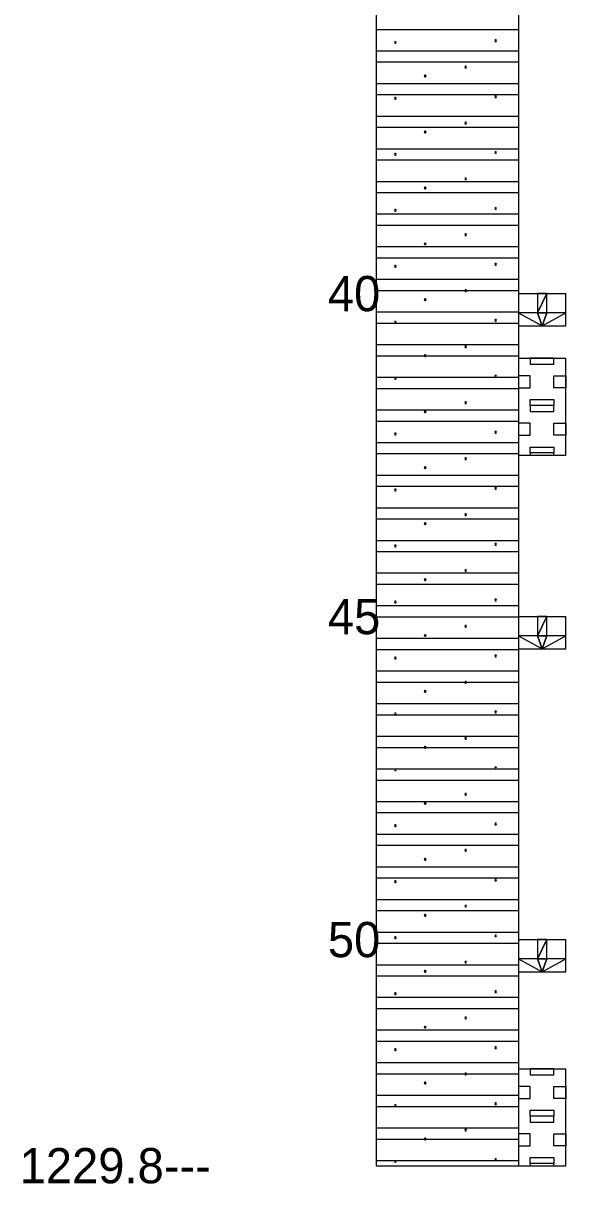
# Model space of a CAD drawing. Extents: x 2150161.5 to 2150203.1, y 143779.5 to 143868.5.
# Drawn here: x 2150190.718 to 2150192.627, y 143817.137 to 143821.22 of the extents above; entities that cross this region are included whole.
import ezdxf

# ---------------------------------------------------------------- set-up
doc = ezdxf.new("R2010")
doc.units = 0
doc.layers.add('Default', color=7, linetype='Continuous')

msp = doc.modelspace()

# ---------------------------------------------------------------- linework, layer by layer
at = {"layer": 'Default'}
for points in [[(2150191.9604, 143829.3595), (2150191.9604, 143817.2004)], [(2150192.4604, 143829.3595), (2150192.4604, 143817.2004)], [(2150191.9604, 143821.1983), (2150192.4604, 143821.1983)], [(2150192.0308, 143821.1521), (2150192.0292, 143821.1549), (2150192.0259, 143821.1549), (2150192.0243, 143821.1521), (2150192.0259, 143821.1492), (2150192.0292, 143821.1492), (2150192.0308, 143821.1521)], [(2150192.3836, 143821.1586), (2150192.3819, 143821.1615), (2150192.3787, 143821.1615), (2150192.377, 143821.1586), (2150192.3787, 143821.1558), (2150192.3819, 143821.1558), (2150192.3836, 143821.1586)], [(2150191.9604, 143821.1228), (2150192.4604, 143821.1228)], [(2150191.9604, 143821.0835), (2150192.4604, 143821.0835)], [(2150192.2781, 143821.0661), (2150192.2764, 143821.0689), (2150192.2731, 143821.0689), (2150192.2715, 143821.0661), (2150192.2731, 143821.0632), (2150192.2764, 143821.0632), (2150192.2781, 143821.0661)], [(2150192.1355, 143821.0342), (2150192.1338, 143821.0371), (2150192.1306, 143821.0371), (2150192.1289, 143821.0342), (2150192.1306, 143821.0314), (2150192.1338, 143821.0314), (2150192.1355, 143821.0342)], [(2150191.9604, 143821.008), (2150192.4604, 143821.008)], [(2150191.9604, 143820.9686), (2150192.4604, 143820.9686)], [(2150192.0308, 143820.9552), (2150192.0292, 143820.9581), (2150192.0259, 143820.9581), (2150192.0243, 143820.9552), (2150192.0259, 143820.9524), (2150192.0292, 143820.9524), (2150192.0308, 143820.9552)], [(2150192.3836, 143820.9617), (2150192.3819, 143820.9646), (2150192.3787, 143820.9646), (2150192.377, 143820.9617), (2150192.3787, 143820.9589), (2150192.3819, 143820.9589), (2150192.3836, 143820.9617)], [(2150191.9604, 143820.8932), (2150192.4604, 143820.8932)], [(2150191.9604, 143820.8538), (2150192.4604, 143820.8538)], [(2150192.2781, 143820.8692), (2150192.2764, 143820.872), (2150192.2731, 143820.872), (2150192.2715, 143820.8692), (2150192.2731, 143820.8664), (2150192.2764, 143820.8664), (2150192.2781, 143820.8692)], [(2150192.1355, 143820.8373), (2150192.1338, 143820.8402), (2150192.1306, 143820.8402), (2150192.1289, 143820.8374), (2150192.1306, 143820.8345), (2150192.1338, 143820.8345), (2150192.1355, 143820.8373)], [(2150191.9604, 143820.7783), (2150192.4604, 143820.7783)], [(2150192.3836, 143820.7649), (2150192.3819, 143820.7678), (2150192.3787, 143820.7678), (2150192.377, 143820.7649), (2150192.3787, 143820.7621), (2150192.3819, 143820.7621), (2150192.3836, 143820.7649)], [(2150191.9604, 143820.739), (2150192.4604, 143820.739)], [(2150192.0308, 143820.7584), (2150192.0292, 143820.7612), (2150192.0259, 143820.7612), (2150192.0243, 143820.7584), (2150192.0259, 143820.7555), (2150192.0292, 143820.7555), (2150192.0308, 143820.7584)], [(2150191.9604, 143820.6635), (2150192.4604, 143820.6635)], [(2150192.1355, 143820.6405), (2150192.1338, 143820.6434), (2150192.1306, 143820.6434), (2150192.1289, 143820.6405), (2150192.1306, 143820.6377), (2150192.1338, 143820.6377), (2150192.1355, 143820.6405)], [(2150192.2781, 143820.6724), (2150192.2764, 143820.6752), (2150192.2731, 143820.6752), (2150192.2715, 143820.6724), (2150192.2731, 143820.6695), (2150192.2764, 143820.6695), (2150192.2781, 143820.6724)], [(2150191.9604, 143820.6241), (2150192.4604, 143820.6241)], [(2150192.0308, 143820.5615), (2150192.0292, 143820.5644), (2150192.0259, 143820.5644), (2150192.0243, 143820.5615), (2150192.0259, 143820.5587), (2150192.0292, 143820.5587), (2150192.0308, 143820.5615)], [(2150192.3836, 143820.568), (2150192.3819, 143820.5709), (2150192.3787, 143820.5709), (2150192.377, 143820.568), (2150192.3787, 143820.5652), (2150192.3819, 143820.5652), (2150192.3836, 143820.568)], [(2150191.9604, 143820.5487), (2150192.4604, 143820.5487)], [(2150191.9604, 143820.5093), (2150192.4604, 143820.5093)], [(2150192.2781, 143820.4755), (2150192.2764, 143820.4783), (2150192.2731, 143820.4783), (2150192.2715, 143820.4755), (2150192.2731, 143820.4727), (2150192.2764, 143820.4727), (2150192.2781, 143820.4755)], [(2150192.1355, 143820.4436), (2150192.1338, 143820.4465), (2150192.1306, 143820.4465), (2150192.1289, 143820.4437), (2150192.1306, 143820.4408), (2150192.1338, 143820.4408), (2150192.1355, 143820.4436)], [(2150191.9604, 143820.4339), (2150192.4604, 143820.4339)], [(2150191.9604, 143820.3945), (2150192.4604, 143820.3945)], [(2150192.0308, 143820.3647), (2150192.0292, 143820.3675), (2150192.0259, 143820.3675), (2150192.0243, 143820.3647), (2150192.0259, 143820.3618), (2150192.0292, 143820.3618), (2150192.0308, 143820.3647)], [(2150192.3836, 143820.3712), (2150192.3819, 143820.3741), (2150192.3787, 143820.3741), (2150192.377, 143820.3712), (2150192.3787, 143820.3684), (2150192.3819, 143820.3684), (2150192.3836, 143820.3712)], [(2150191.9604, 143820.319), (2150192.4604, 143820.319)], [(2150191.9604, 143820.2797), (2150192.4604, 143820.2797)], [(2150192.2781, 143820.2787), (2150192.2764, 143820.2815), (2150192.2731, 143820.2815), (2150192.2715, 143820.2787), (2150192.2731, 143820.2758), (2150192.2764, 143820.2758), (2150192.2781, 143820.2787)], [(2150192.1355, 143820.2468), (2150192.1338, 143820.2497), (2150192.1306, 143820.2497), (2150192.1289, 143820.2468), (2150192.1306, 143820.244), (2150192.1338, 143820.244), (2150192.1355, 143820.2468)], [(2150192.4604, 143820.2686), (2150192.6271, 143820.2686)], [(2150192.6271, 143820.155), (2150192.6271, 143820.2686)], [(2150191.9604, 143820.2042), (2150192.4604, 143820.2042)], [(2150191.9604, 143820.1648), (2150192.4604, 143820.1648)], [(2150192.0308, 143820.1678), (2150192.0292, 143820.1707), (2150192.0259, 143820.1707), (2150192.0243, 143820.1678), (2150192.0259, 143820.165), (2150192.0292, 143820.165), (2150192.0308, 143820.1678)], [(2150192.3836, 143820.1743), (2150192.3819, 143820.1772), (2150192.3787, 143820.1772), (2150192.377, 143820.1743), (2150192.3787, 143820.1715), (2150192.3819, 143820.1715), (2150192.3836, 143820.1743)], [(2150192.4604, 143820.155), (2150192.6271, 143820.155)], [(2150191.9604, 143820.0894), (2150192.4604, 143820.0894)], [(2150192.2781, 143820.0818), (2150192.2764, 143820.0846), (2150192.2731, 143820.0846), (2150192.2715, 143820.0818), (2150192.2731, 143820.079), (2150192.2764, 143820.079), (2150192.2781, 143820.0818)], [(2150191.9604, 143820.05), (2150192.4604, 143820.05)], [(2150192.1355, 143820.0499), (2150192.1338, 143820.0528), (2150192.1306, 143820.0528), (2150192.1289, 143820.05), (2150192.1306, 143820.0471), (2150192.1338, 143820.0471), (2150192.1355, 143820.0499)], [(2150192.4604, 143820.0413), (2150192.6271, 143820.0413)], [(2150192.6271, 143819.7004), (2150192.6271, 143820.0413)], [(2150191.9604, 143819.9745), (2150192.4604, 143819.9745)], [(2150192.0308, 143819.971), (2150192.0292, 143819.9738), (2150192.0259, 143819.9738), (2150192.0243, 143819.971), (2150192.0259, 143819.9681), (2150192.0292, 143819.9681), (2150192.0308, 143819.971)], [(2150192.3836, 143819.9775), (2150192.3819, 143819.9804), (2150192.3787, 143819.9804), (2150192.377, 143819.9775), (2150192.3787, 143819.9747), (2150192.3819, 143819.9747), (2150192.3836, 143819.9775)], [(2150191.9604, 143819.9352), (2150192.4604, 143819.9352)], [(2150192.2781, 143819.885), (2150192.2764, 143819.8878), (2150192.2731, 143819.8878), (2150192.2715, 143819.885), (2150192.2731, 143819.8821), (2150192.2764, 143819.8821), (2150192.2781, 143819.885)], [(2150191.9604, 143819.8597), (2150192.4604, 143819.8597)], [(2150192.1355, 143819.8531), (2150192.1338, 143819.856), (2150192.1306, 143819.856), (2150192.1289, 143819.8531), (2150192.1306, 143819.8503), (2150192.1338, 143819.8503), (2150192.1355, 143819.8531)], [(2150191.9604, 143819.8203), (2150192.4604, 143819.8203)], [(2150191.9604, 143819.7449), (2150192.4604, 143819.7449)], [(2150192.0308, 143819.7741), (2150192.0292, 143819.777), (2150192.0259, 143819.777), (2150192.0243, 143819.7741), (2150192.0259, 143819.7713), (2150192.0292, 143819.7713), (2150192.0308, 143819.7741)], [(2150192.3836, 143819.7806), (2150192.3819, 143819.7835), (2150192.3787, 143819.7835), (2150192.377, 143819.7806), (2150192.3787, 143819.7778), (2150192.3819, 143819.7778), (2150192.3836, 143819.7806)], [(2150191.9604, 143819.7055), (2150192.4604, 143819.7055)], [(2150192.2781, 143819.6881), (2150192.2764, 143819.6909), (2150192.2731, 143819.6909), (2150192.2715, 143819.6881), (2150192.2731, 143819.6853), (2150192.2764, 143819.6853), (2150192.2781, 143819.6881)], [(2150192.4604, 143819.7004), (2150192.6271, 143819.7004)], [(2150191.9604, 143819.63), (2150192.4604, 143819.63)], [(2150192.1355, 143819.6562), (2150192.1338, 143819.6591), (2150192.1306, 143819.6591), (2150192.1289, 143819.6563), (2150192.1306, 143819.6534), (2150192.1338, 143819.6534), (2150192.1355, 143819.6562)], [(2150191.9604, 143819.5907), (2150192.4604, 143819.5907)], [(2150192.0308, 143819.5773), (2150192.0292, 143819.5801), (2150192.0259, 143819.5801), (2150192.0243, 143819.5773), (2150192.0259, 143819.5744), (2150192.0292, 143819.5744), (2150192.0308, 143819.5773)], [(2150192.3836, 143819.5838), (2150192.3819, 143819.5867), (2150192.3787, 143819.5867), (2150192.377, 143819.5838), (2150192.3787, 143819.581), (2150192.3819, 143819.581), (2150192.3836, 143819.5838)], [(2150191.9604, 143819.5152), (2150192.4604, 143819.5152)], [(2150191.9604, 143819.4758), (2150192.4604, 143819.4758)], [(2150192.1355, 143819.4594), (2150192.1338, 143819.4623), (2150192.1306, 143819.4623), (2150192.1289, 143819.4594), (2150192.1306, 143819.4566), (2150192.1338, 143819.4566), (2150192.1355, 143819.4594)], [(2150192.2781, 143819.4913), (2150192.2764, 143819.4941), (2150192.2731, 143819.4941), (2150192.2715, 143819.4913), (2150192.2731, 143819.4884), (2150192.2764, 143819.4884), (2150192.2781, 143819.4913)], [(2150191.9604, 143819.4004), (2150192.4604, 143819.4004)], [(2150192.0308, 143819.3804), (2150192.0292, 143819.3833), (2150192.0259, 143819.3833), (2150192.0243, 143819.3804), (2150192.0259, 143819.3776), (2150192.0292, 143819.3776), (2150192.0308, 143819.3804)], [(2150192.3836, 143819.3869), (2150192.3819, 143819.3898), (2150192.3787, 143819.3898), (2150192.377, 143819.3869), (2150192.3787, 143819.3841), (2150192.3819, 143819.3841), (2150192.3836, 143819.3869)], [(2150191.9604, 143819.361), (2150192.4604, 143819.361)], [(2150192.2781, 143819.2944), (2150192.2764, 143819.2972), (2150192.2731, 143819.2972), (2150192.2715, 143819.2944), (2150192.2731, 143819.2916), (2150192.2764, 143819.2916), (2150192.2781, 143819.2944)], [(2150191.9604, 143819.2856), (2150192.4604, 143819.2856)], [(2150192.1355, 143819.2625), (2150192.1338, 143819.2654), (2150192.1306, 143819.2654), (2150192.1289, 143819.2626), (2150192.1306, 143819.2597), (2150192.1338, 143819.2597), (2150192.1355, 143819.2625)], [(2150191.9604, 143819.2462), (2150192.4604, 143819.2462)], [(2150192.0308, 143819.1836), (2150192.0292, 143819.1864), (2150192.0259, 143819.1864), (2150192.0243, 143819.1836), (2150192.0259, 143819.1807), (2150192.0292, 143819.1807), (2150192.0308, 143819.1836)], [(2150192.3836, 143819.1901), (2150192.3819, 143819.193), (2150192.3787, 143819.193), (2150192.377, 143819.1901), (2150192.3787, 143819.1873), (2150192.3819, 143819.1873), (2150192.3836, 143819.1901)], [(2150191.9604, 143819.1707), (2150192.4604, 143819.1707)], [(2150191.9604, 143819.1314), (2150192.4604, 143819.1314)], [(2150192.4604, 143819.1323), (2150192.6271, 143819.1323)], [(2150192.6271, 143819.0186), (2150192.6271, 143819.1323)], [(2150192.2781, 143819.0976), (2150192.2764, 143819.1004), (2150192.2731, 143819.1004), (2150192.2715, 143819.0976), (2150192.2731, 143819.0947), (2150192.2764, 143819.0947), (2150192.2781, 143819.0976)], [(2150191.9604, 143819.0559), (2150192.4604, 143819.0559)], [(2150192.1355, 143819.0657), (2150192.1338, 143819.0686), (2150192.1306, 143819.0686), (2150192.1289, 143819.0657), (2150192.1306, 143819.0629), (2150192.1338, 143819.0629), (2150192.1355, 143819.0657)], [(2150191.9604, 143819.0165), (2150192.4604, 143819.0165)], [(2150192.4604, 143819.0186), (2150192.6271, 143819.0186)], [(2150192.0308, 143818.9867), (2150192.0292, 143818.9896), (2150192.0259, 143818.9896), (2150192.0243, 143818.9867), (2150192.0259, 143818.9839), (2150192.0292, 143818.9839), (2150192.0308, 143818.9867)], [(2150192.3836, 143818.9932), (2150192.3819, 143818.9961), (2150192.3787, 143818.9961), (2150192.377, 143818.9932), (2150192.3787, 143818.9904), (2150192.3819, 143818.9904), (2150192.3836, 143818.9932)], [(2150191.9604, 143818.9411), (2150192.4604, 143818.9411)], [(2150191.9604, 143818.9017), (2150192.4604, 143818.9017)], [(2150192.2781, 143818.9007), (2150192.2764, 143818.9035), (2150192.2731, 143818.9035), (2150192.2715, 143818.9007), (2150192.2731, 143818.8979), (2150192.2764, 143818.8979), (2150192.2781, 143818.9007)], [(2150192.1355, 143818.8688), (2150192.1338, 143818.8717), (2150192.1306, 143818.8717), (2150192.1289, 143818.8689), (2150192.1306, 143818.866), (2150192.1338, 143818.866), (2150192.1355, 143818.8688)], [(2150191.9604, 143818.8262), (2150192.4604, 143818.8262)], [(2150191.9604, 143818.7869), (2150192.4604, 143818.7869)], [(2150192.0308, 143818.7899), (2150192.0292, 143818.7927), (2150192.0259, 143818.7927), (2150192.0243, 143818.7899), (2150192.0259, 143818.787), (2150192.0292, 143818.787), (2150192.0308, 143818.7899)], [(2150192.3836, 143818.7964), (2150192.3819, 143818.7993), (2150192.3787, 143818.7993), (2150192.377, 143818.7964), (2150192.3787, 143818.7936), (2150192.3819, 143818.7936), (2150192.3836, 143818.7964)], [(2150191.9604, 143818.7114), (2150192.4604, 143818.7114)], [(2150192.2781, 143818.7039), (2150192.2764, 143818.7067), (2150192.2731, 143818.7067), (2150192.2715, 143818.7039), (2150192.2731, 143818.701), (2150192.2764, 143818.701), (2150192.2781, 143818.7039)], [(2150191.9604, 143818.672), (2150192.4604, 143818.672)], [(2150192.1355, 143818.672), (2150192.1338, 143818.6749), (2150192.1306, 143818.6749), (2150192.1289, 143818.672), (2150192.1306, 143818.6692), (2150192.1338, 143818.6692), (2150192.1355, 143818.672)], [(2150192.3836, 143818.5995), (2150192.3819, 143818.6024), (2150192.3787, 143818.6024), (2150192.377, 143818.5995), (2150192.3787, 143818.5967), (2150192.3819, 143818.5967), (2150192.3836, 143818.5995)], [(2150191.9604, 143818.5966), (2150192.4604, 143818.5966)], [(2150192.0308, 143818.593), (2150192.0292, 143818.5959), (2150192.0259, 143818.5959), (2150192.0243, 143818.593), (2150192.0259, 143818.5902), (2150192.0292, 143818.5902), (2150192.0308, 143818.593)], [(2150191.9604, 143818.5572), (2150192.4604, 143818.5572)], [(2150191.9604, 143818.4818), (2150192.4604, 143818.4818)], [(2150192.1355, 143818.4751), (2150192.1338, 143818.478), (2150192.1306, 143818.478), (2150192.1289, 143818.4752), (2150192.1306, 143818.4723), (2150192.1338, 143818.4723), (2150192.1355, 143818.4751)], [(2150192.2781, 143818.507), (2150192.2764, 143818.5098), (2150192.2731, 143818.5098), (2150192.2715, 143818.507), (2150192.2731, 143818.5042), (2150192.2764, 143818.5042), (2150192.2781, 143818.507)], [(2150191.9604, 143818.4424), (2150192.4604, 143818.4424)], [(2150192.0308, 143818.3962), (2150192.0292, 143818.399), (2150192.0259, 143818.399), (2150192.0243, 143818.3962), (2150192.0259, 143818.3933), (2150192.0292, 143818.3933), (2150192.0308, 143818.3962)], [(2150192.3836, 143818.4027), (2150192.3819, 143818.4056), (2150192.3787, 143818.4056), (2150192.377, 143818.4027), (2150192.3787, 143818.3999), (2150192.3819, 143818.3999), (2150192.3836, 143818.4027)], [(2150191.9604, 143818.3669), (2150192.4604, 143818.3669)], [(2150191.9604, 143818.3276), (2150192.4604, 143818.3276)], [(2150192.1355, 143818.2783), (2150192.1338, 143818.2812), (2150192.1306, 143818.2812), (2150192.1289, 143818.2783), (2150192.1306, 143818.2755), (2150192.1338, 143818.2755), (2150192.1355, 143818.2783)], [(2150192.2781, 143818.3102), (2150192.2764, 143818.313), (2150192.2731, 143818.313), (2150192.2715, 143818.3102), (2150192.2731, 143818.3073), (2150192.2764, 143818.3073), (2150192.2781, 143818.3102)], [(2150191.9604, 143818.2521), (2150192.4604, 143818.2521)], [(2150191.9604, 143818.2127), (2150192.4604, 143818.2127)], [(2150192.0308, 143818.1993), (2150192.0292, 143818.2022), (2150192.0259, 143818.2022), (2150192.0243, 143818.1993), (2150192.0259, 143818.1965), (2150192.0292, 143818.1965), (2150192.0308, 143818.1993)], [(2150192.3836, 143818.2058), (2150192.3819, 143818.2087), (2150192.3787, 143818.2087), (2150192.377, 143818.2058), (2150192.3787, 143818.203), (2150192.3819, 143818.203), (2150192.3836, 143818.2058)], [(2150191.9604, 143818.1373), (2150192.4604, 143818.1373)], [(2150192.2781, 143818.1133), (2150192.2764, 143818.1161), (2150192.2731, 143818.1161), (2150192.2715, 143818.1133), (2150192.2731, 143818.1105), (2150192.2764, 143818.1105), (2150192.2781, 143818.1133)], [(2150191.9604, 143818.0979), (2150192.4604, 143818.0979)], [(2150192.1355, 143818.0814), (2150192.1338, 143818.0843), (2150192.1306, 143818.0843), (2150192.1289, 143818.0815), (2150192.1306, 143818.0786), (2150192.1338, 143818.0786), (2150192.1355, 143818.0814)], [(2150191.9604, 143818.0224), (2150192.4604, 143818.0224)], [(2150192.0308, 143818.0025), (2150192.0292, 143818.0053), (2150192.0259, 143818.0053), (2150192.0243, 143818.0025), (2150192.0259, 143817.9996), (2150192.0292, 143817.9996), (2150192.0308, 143818.0025)], [(2150192.3836, 143818.009), (2150192.3819, 143818.0119), (2150192.3787, 143818.0119), (2150192.377, 143818.009), (2150192.3787, 143818.0062), (2150192.3819, 143818.0062), (2150192.3836, 143818.009)], [(2150192.4604, 143817.9959), (2150192.6271, 143817.9959)], [(2150192.6271, 143817.8823), (2150192.6271, 143817.9959)], [(2150191.9604, 143817.9831), (2150192.4604, 143817.9831)], [(2150191.9604, 143817.9076), (2150192.4604, 143817.9076)], [(2150192.2781, 143817.9165), (2150192.2764, 143817.9193), (2150192.2731, 143817.9193), (2150192.2715, 143817.9165), (2150192.2731, 143817.9136), (2150192.2764, 143817.9136), (2150192.2781, 143817.9165)], [(2150191.9604, 143817.8682), (2150192.4604, 143817.8682)], [(2150192.1355, 143817.8846), (2150192.1338, 143817.8875), (2150192.1306, 143817.8875), (2150192.1289, 143817.8846), (2150192.1306, 143817.8818), (2150192.1338, 143817.8818), (2150192.1355, 143817.8846)], [(2150192.4604, 143817.8823), (2150192.6271, 143817.8823)], [(2150191.9604, 143817.7928), (2150192.4604, 143817.7928)], [(2150192.0308, 143817.8056), (2150192.0292, 143817.8085), (2150192.0259, 143817.8085), (2150192.0243, 143817.8056), (2150192.0259, 143817.8028), (2150192.0292, 143817.8028), (2150192.0308, 143817.8056)], [(2150192.3836, 143817.8121), (2150192.3819, 143817.815), (2150192.3787, 143817.815), (2150192.377, 143817.8121), (2150192.3787, 143817.8093), (2150192.3819, 143817.8093), (2150192.3836, 143817.8121)], [(2150191.9604, 143817.7534), (2150192.4604, 143817.7534)], [(2150192.2781, 143817.7196), (2150192.2764, 143817.7224), (2150192.2731, 143817.7224), (2150192.2715, 143817.7196), (2150192.2731, 143817.7168), (2150192.2764, 143817.7168), (2150192.2781, 143817.7196)], [(2150191.9604, 143817.678), (2150192.4604, 143817.678)], [(2150192.1355, 143817.6877), (2150192.1338, 143817.6906), (2150192.1306, 143817.6906), (2150192.1289, 143817.6878), (2150192.1306, 143817.6849), (2150192.1338, 143817.6849), (2150192.1355, 143817.6877)], [(2150191.9604, 143817.6386), (2150192.4604, 143817.6386)], [(2150192.0308, 143817.6088), (2150192.0292, 143817.6116), (2150192.0259, 143817.6116), (2150192.0243, 143817.6088), (2150192.0259, 143817.6059), (2150192.0292, 143817.6059), (2150192.0308, 143817.6088)], [(2150192.3836, 143817.6153), (2150192.3819, 143817.6182), (2150192.3787, 143817.6182), (2150192.377, 143817.6153), (2150192.3787, 143817.6125), (2150192.3819, 143817.6125), (2150192.3836, 143817.6153)], [(2150191.9604, 143817.5631), (2150192.4604, 143817.5631)], [(2150192.4604, 143817.5413), (2150192.6271, 143817.5413)], [(2150192.6271, 143817.2004), (2150192.6271, 143817.5413)], [(2150191.9604, 143817.5238), (2150192.4604, 143817.5238)], [(2150192.2781, 143817.5228), (2150192.2764, 143817.5256), (2150192.2731, 143817.5256), (2150192.2715, 143817.5228), (2150192.2731, 143817.5199), (2150192.2764, 143817.5199), (2150192.2781, 143817.5228)], [(2150192.1355, 143817.4909), (2150192.1338, 143817.4938), (2150192.1306, 143817.4938), (2150192.1289, 143817.4909), (2150192.1306, 143817.4881), (2150192.1338, 143817.4881), (2150192.1355, 143817.4909)], [(2150191.9604, 143817.4483), (2150192.4604, 143817.4483)], [(2150192.3836, 143817.4184), (2150192.3819, 143817.4213), (2150192.3787, 143817.4213), (2150192.377, 143817.4184), (2150192.3787, 143817.4156), (2150192.3819, 143817.4156), (2150192.3836, 143817.4184)], [(2150191.9604, 143817.4089), (2150192.4604, 143817.4089)], [(2150192.0308, 143817.4119), (2150192.0292, 143817.4148), (2150192.0259, 143817.4148), (2150192.0243, 143817.4119), (2150192.0259, 143817.4091), (2150192.0292, 143817.4091), (2150192.0308, 143817.4119)], [(2150191.9604, 143817.3335), (2150192.4604, 143817.3335)], [(2150191.9604, 143817.2941), (2150192.4604, 143817.2941)], [(2150192.1355, 143817.294), (2150192.1338, 143817.2969), (2150192.1306, 143817.2969), (2150192.1289, 143817.2941), (2150192.1306, 143817.2912), (2150192.1338, 143817.2912), (2150192.1355, 143817.294)], [(2150192.2781, 143817.3259), (2150192.2764, 143817.3287), (2150192.2731, 143817.3287), (2150192.2715, 143817.3259), (2150192.2731, 143817.3231), (2150192.2764, 143817.3231), (2150192.2781, 143817.3259)], [(2150191.9604, 143817.2186), (2150192.4604, 143817.2186)], [(2150192.0308, 143817.2151), (2150192.0292, 143817.2179), (2150192.0259, 143817.2179), (2150192.0243, 143817.2151), (2150192.0259, 143817.2122), (2150192.0292, 143817.2122), (2150192.0308, 143817.2151)], [(2150192.3836, 143817.2216), (2150192.3819, 143817.2245), (2150192.3787, 143817.2245), (2150192.377, 143817.2216), (2150192.3787, 143817.2188), (2150192.3819, 143817.2188), (2150192.3836, 143817.2216)], [(2150191.9604, 143817.2004), (2150192.4604, 143817.2004)], [(2150192.4604, 143817.2004), (2150192.6271, 143817.2004)]]:
    msp.add_lwpolyline(points, dxfattribs=at)
for points in [[(2150192.5271, 143820.2004), (2150192.5604, 143820.2004), (2150192.5604, 143820.2686), (2150192.5271, 143820.2004)], [(2150192.5271, 143820.2004), (2150192.5604, 143820.2686), (2150192.5271, 143820.2686), (2150192.5271, 143820.2004)], [(2150192.5271, 143820.2004), (2150192.4604, 143820.2004), (2150192.5437, 143820.155), (2150192.5271, 143820.2004)], [(2150192.5271, 143820.2004), (2150192.5437, 143820.155), (2150192.5604, 143820.2004), (2150192.5271, 143820.2004)], [(2150192.5437, 143820.155), (2150192.6271, 143820.2004), (2150192.5604, 143820.2004), (2150192.5437, 143820.155)], [(2150192.5021, 143820.0413), (2150192.5021, 143820.0205), (2150192.5854, 143820.0205), (2150192.5854, 143820.0413)], [(2150192.4604, 143819.9372), (2150192.5021, 143819.9372), (2150192.5021, 143819.9788), (2150192.4604, 143819.9788)], [(2150192.6271, 143819.9372), (2150192.5854, 143819.9372), (2150192.5854, 143819.9788), (2150192.6271, 143819.9788)], [(2150192.5021, 143819.8747), (2150192.5021, 143819.8955), (2150192.5854, 143819.8955), (2150192.5854, 143819.8747)], [(2150192.5021, 143819.8747), (2150192.5021, 143819.8538), (2150192.5854, 143819.8538), (2150192.5854, 143819.8747)], [(2150192.4604, 143819.7705), (2150192.5021, 143819.7705), (2150192.5021, 143819.8122), (2150192.4604, 143819.8122)], [(2150192.6271, 143819.7705), (2150192.5854, 143819.7705), (2150192.5854, 143819.8122), (2150192.6271, 143819.8122)], [(2150192.5021, 143819.708), (2150192.5021, 143819.7288), (2150192.5854, 143819.7288), (2150192.5854, 143819.708)], [(2150192.5854, 143819.708), (2150192.5021, 143819.708), (2150192.5021, 143819.7004), (2150192.5854, 143819.7004)], [(2150192.5271, 143819.0641), (2150192.5604, 143819.0641), (2150192.5604, 143819.1323), (2150192.5271, 143819.0641)], [(2150192.5271, 143819.0641), (2150192.5604, 143819.1323), (2150192.5271, 143819.1323), (2150192.5271, 143819.0641)], [(2150192.5271, 143819.0641), (2150192.4604, 143819.0641), (2150192.5437, 143819.0186), (2150192.5271, 143819.0641)], [(2150192.5271, 143819.0641), (2150192.5437, 143819.0186), (2150192.5604, 143819.0641), (2150192.5271, 143819.0641)], [(2150192.5437, 143819.0186), (2150192.6271, 143819.0641), (2150192.5604, 143819.0641), (2150192.5437, 143819.0186)], [(2150192.5271, 143817.9277), (2150192.5604, 143817.9277), (2150192.5604, 143817.9959), (2150192.5271, 143817.9277)], [(2150192.5271, 143817.9277), (2150192.5604, 143817.9959), (2150192.5271, 143817.9959), (2150192.5271, 143817.9277)], [(2150192.5271, 143817.9277), (2150192.4604, 143817.9277), (2150192.5437, 143817.8823), (2150192.5271, 143817.9277)], [(2150192.5271, 143817.9277), (2150192.5437, 143817.8823), (2150192.5604, 143817.9277), (2150192.5271, 143817.9277)], [(2150192.5437, 143817.8823), (2150192.6271, 143817.9277), (2150192.5604, 143817.9277), (2150192.5437, 143817.8823)], [(2150192.5021, 143817.5413), (2150192.5021, 143817.5205), (2150192.5854, 143817.5205), (2150192.5854, 143817.5413)], [(2150192.4604, 143817.4372), (2150192.5021, 143817.4372), (2150192.5021, 143817.4788), (2150192.4604, 143817.4788)], [(2150192.6271, 143817.4372), (2150192.5854, 143817.4372), (2150192.5854, 143817.4788), (2150192.6271, 143817.4788)], [(2150192.5021, 143817.3747), (2150192.5021, 143817.3955), (2150192.5854, 143817.3955), (2150192.5854, 143817.3747)], [(2150192.5021, 143817.3747), (2150192.5021, 143817.3538), (2150192.5854, 143817.3538), (2150192.5854, 143817.3747)], [(2150192.4604, 143817.2705), (2150192.5021, 143817.2705), (2150192.5021, 143817.3122), (2150192.4604, 143817.3122)], [(2150192.6271, 143817.2705), (2150192.5854, 143817.2705), (2150192.5854, 143817.3122), (2150192.6271, 143817.3122)], [(2150192.5021, 143817.208), (2150192.5021, 143817.2288), (2150192.5854, 143817.2288), (2150192.5854, 143817.208)], [(2150192.5854, 143817.208), (2150192.5021, 143817.208), (2150192.5021, 143817.2004), (2150192.5854, 143817.2004)]]:
    msp.add_lwpolyline(points, close=True, dxfattribs=at)

# ---------------------------------------------------------------- texts
for s, p in [('40', (2150191.79, 143820.2066)), ('45', (2150191.79, 143819.0703)), ('50', (2150191.79, 143817.9339)), ('1229.8---', (2150190.7055, 143817.1384))]:
    msp.add_text(s, height=0.124, dxfattribs=at).set_placement(p)

doc.saveas('drawing.dxf')
